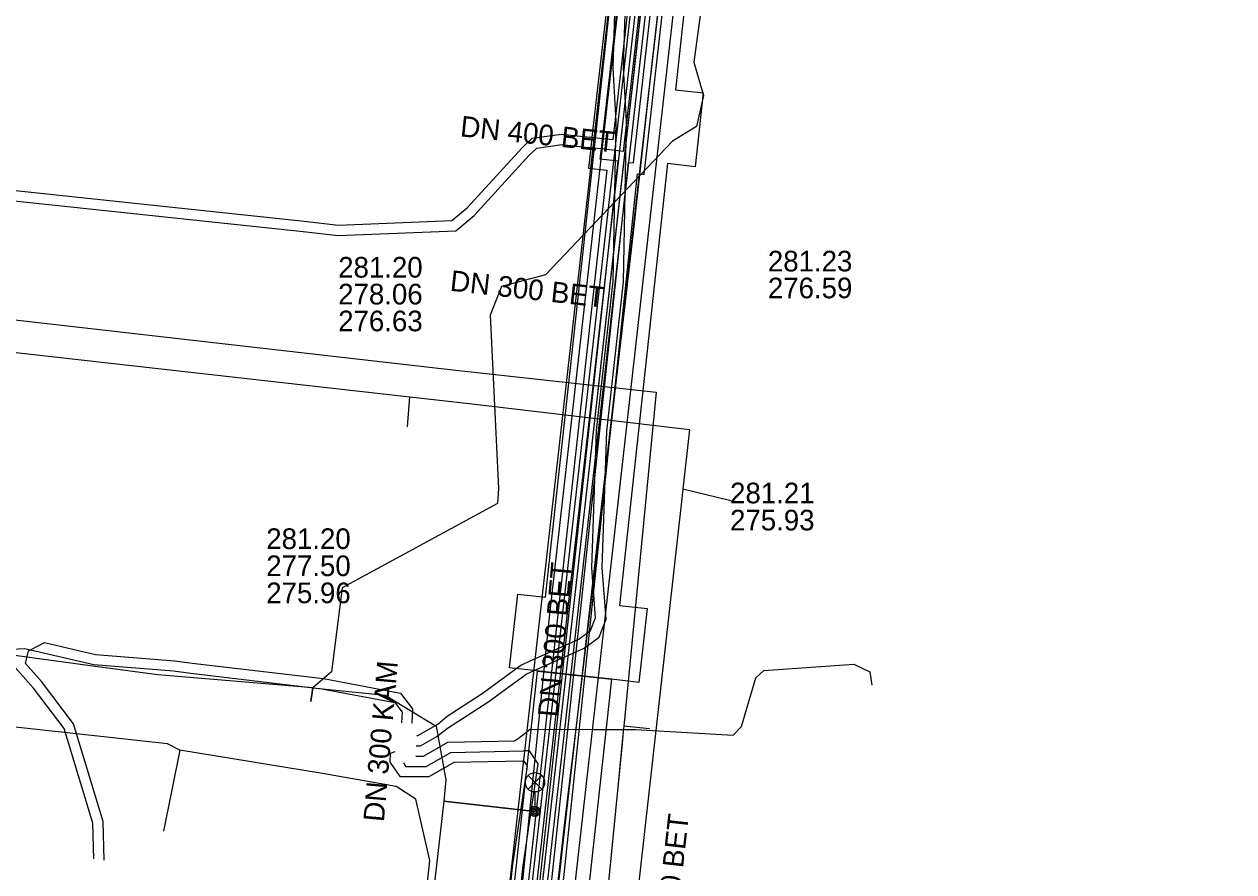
# Model space of a CAD drawing. Extents: x -595540 to -593988, y -1160850 to -1159202.
# Drawn here: x -594128.31 to -594081.46, y -1160371.96 to -1160339.11 of the extents above; entities that cross this region are included whole.
import ezdxf

# ---------------------------------------------------------------- set-up
doc = ezdxf.new("R2010")
doc.units = 0
for name, color, linetype in [('BVK-DESTOVA_popisy', 7, 'Continuous'), ('BVK-DESTOVA_trasa sítě', 7, 'Continuous'), ('BVK-KANALIZACE_ vyřazená trasa sítě', 7, 'Continuous'), ('BVK-SPLASKOVA_popisy', 7, 'Continuous'), ('BVK-SPLASKOVA_trasa sítě', 7, 'Continuous'), ('BVK-VODOVOD_trasa sítě', 7, 'Continuous'), ('BVK-VODOVOD_trasa zrušené sítě', 7, 'Continuous'), ('CETIN_kabel podzemní', 7, 'Continuous'), ('DESTOVA_trasa neprovozované sítě', 7, 'Continuous'), ('DSP-NN-TEPLARNY_kabel', 7, 'Continuous'), ('EON-NN_kabel', 7, 'Continuous'), ('EON-VN_kabel', 7, 'Continuous'), ('SPLASKOVA_neprovozovaná  trasa sítě', 7, 'Continuous'), ('TEPLARNY-ELEKTRO_kabel', 7, 'Continuous'), ('TEPLARNY-HORKOVODY_trasa sítě', 7, 'Continuous'), ('TEPLARNY-HORKOVODY_trasa sítě obvodem', 7, 'Continuous'), ('TSB_kabel VO', 7, 'Continuous'), ('TSB_kolektor', 7, 'Continuous'), ('TSB_lampy VO', 7, 'Continuous')]:
    doc.layers.add(name, color=color, linetype=linetype)

msp = doc.modelspace()

# ---------------------------------------------------------------- linework, layer by layer
at = {"layer": 'BVK-DESTOVA_popisy'}
for p, q in [((-594100.971, -1160357.808), (-594100.971, -1160357.808)), ((-594118.938, -1160360.103), (-594118.938, -1160360.103))]:
    msp.add_line(p, q, dxfattribs=at)
at = {"layer": 'BVK-DESTOVA_trasa sítě'}
msp.add_line((-594111.075, -1160353.812), (-594102.539, -1160354.822), dxfattribs=at)
for points in [[(-594159.261, -1160348.383), (-594113.381, -1160353.552), (-594111.075, -1160353.812)], [(-594102.539, -1160354.822), (-594102.799, -1160357.137), (-594102.811, -1160357.247), (-594102.852, -1160357.611), (-594105.877, -1160384.565), (-594105.882, -1160384.615), (-594105.901, -1160384.78), (-594106.212, -1160387.553)]]:
    msp.add_lwpolyline(points, dxfattribs=at)
at = {"layer": 'BVK-KANALIZACE_ vyřazená trasa sítě'}
msp.add_lwpolyline([(-594105.111, -1160366.52), (-594105.157, -1160366.996), (-594105.336, -1160368.828)], dxfattribs=at)
at = {"layer": 'BVK-SPLASKOVA_popisy'}
for p, q in [((-594116.151, -1160348.135), (-594116.151, -1160348.135)), ((-594099.507, -1160347.896), (-594099.507, -1160347.896))]:
    msp.add_line(p, q, dxfattribs=at)
at = {"layer": 'BVK-SPLASKOVA_trasa sítě'}
for p, q in [((-594159.664, -1160347.043), (-594111.588, -1160352.525)), ((-594111.588, -1160352.525), (-594103.829, -1160353.38)), ((-594105.11, -1160366.52), (-594105.33, -1160368.81)), ((-594105.33, -1160368.81), (-594107.088, -1160386.792))]:
    msp.add_line(p, q, dxfattribs=at)
msp.add_lwpolyline([(-594103.829, -1160353.38), (-594105.09, -1160366.319), (-594105.11, -1160366.52)], dxfattribs=at)
at = {"layer": 'BVK-VODOVOD_trasa sítě'}
msp.add_lwpolyline([(-594103.42, -1160335.63), (-594104.1, -1160341.57), (-594104.76, -1160347.52), (-594105.45, -1160353.45), (-594106.12, -1160359.4), (-594106.82, -1160365.34), (-594107.38, -1160370.05), (-594107.74, -1160373.14), (-594107.936, -1160374.896), (-594107.96, -1160375.11), (-594108.36, -1160378.71), (-594108.45, -1160379.55), (-594109.1, -1160385.5), (-594109.66, -1160390.25), (-594109.85, -1160391.65), (-594110.51, -1160397.57), (-594111.2, -1160403.53), (-594111.87, -1160409.48)], dxfattribs=at)
at = {"layer": 'BVK-VODOVOD_trasa zrušené sítě'}
msp.add_lwpolyline([(-594115.62, -1160443.55), (-594109.61, -1160390.38), (-594108.22, -1160378.32), (-594107.91, -1160375.21), (-594107.884, -1160374.982), (-594107.47, -1160371.19), (-594099.17, -1160298.41), (-594097.23, -1160281.2), (-594094.37, -1160256.41), (-594088.99, -1160208), (-594087.61, -1160195.33), (-594087.25, -1160191.91), (-594085.5, -1160175.7), (-594082.16, -1160145.34)], dxfattribs=at)
at = {"layer": 'CETIN_kabel podzemní'}
for points in [[(-594107.97, -1160362.1), (-594096.35, -1160259)], [(-594109.14, -1160373.71), (-594107.97, -1160362.1)], [(-594122.28, -1160367.25), (-594122.76, -1160367), (-594126.06, -1160366.64), (-594143.72, -1160364.72)], [(-594122.28, -1160367.25), (-594122.92, -1160370.39)], [(-594116.76, -1160368.15), (-594122.28, -1160367.25)], [(-594112.78, -1160373.21), (-594112.6, -1160371.52), (-594113.15, -1160369.15), (-594113.9, -1160368.66), (-594116.76, -1160368.15)]]:
    msp.add_lwpolyline(points, dxfattribs=at)
at = {"layer": 'DESTOVA_trasa neprovozované sítě'}
for p, q in [((-594113.467, -1160354.716), (-594113.381, -1160353.552)), ((-594100.569, -1160357.672), (-594102.799, -1160357.137))]:
    msp.add_line(p, q, dxfattribs=at)
at = {"layer": 'DSP-NN-TEPLARNY_kabel'}
for points in [[(-594121.143, -1160464.161), (-594118.761, -1160464.427), (-594112.865, -1160411.563), (-594119.56, -1160410.802), (-594119.143, -1160407.127), (-594112.454, -1160407.887), (-594102.843, -1160322.736), (-594109.531, -1160321.976), (-594109.114, -1160318.301), (-594102.425, -1160319.061), (-594092.133, -1160228.53), (-594097.433, -1160227.929), (-594097.016, -1160224.253), (-594091.712, -1160224.855), (-594085.261, -1160166.749), (-594090.048, -1160166.163), (-594089.626, -1160162.68), (-594084.872, -1160163.243), (-594081.459, -1160132.499), (-594087.185, -1160131.862)], [(-594087.208, -1160132.061), (-594081.68, -1160132.675), (-594085.05, -1160163.028), (-594089.778, -1160162.457), (-594090.247, -1160166.304), (-594085.499, -1160166.867), (-594091.888, -1160224.634), (-594097.192, -1160224.032), (-594097.654, -1160228.105), (-594092.355, -1160228.706), (-594102.601, -1160318.839), (-594109.29, -1160318.079), (-594109.753, -1160322.152), (-594103.064, -1160322.912), (-594112.631, -1160407.665), (-594119.319, -1160406.905), (-594119.782, -1160410.978), (-594113.086, -1160411.739), (-594118.938, -1160464.206), (-594121.121, -1160463.962)], [(-594121.187, -1160464.559), (-594118.408, -1160464.869), (-594112.423, -1160411.211), (-594119.118, -1160410.45), (-594118.791, -1160407.569), (-594112.102, -1160408.329), (-594102.401, -1160322.384), (-594109.089, -1160321.624), (-594108.762, -1160318.743), (-594102.073, -1160319.503), (-594091.691, -1160228.178)], [(-594091.912, -1160228.354), (-594102.249, -1160319.282), (-594108.938, -1160318.522), (-594109.31, -1160321.8), (-594102.622, -1160322.56), (-594112.278, -1160408.108), (-594118.967, -1160407.348), (-594119.339, -1160410.626), (-594112.644, -1160411.387), (-594118.584, -1160464.648), (-594121.165, -1160464.36)]]:
    msp.add_lwpolyline(points, dxfattribs=at)
at = {"layer": 'EON-NN_kabel'}
for points in [[(-594108.673, -1160364.211), (-594106.628, -1160363.298), (-594106.048, -1160362.869), (-594105.776, -1160362.176), (-594105.923, -1160360.172), (-594105.745, -1160354.883), (-594105.1, -1160349.1), (-594104.988, -1160342.873), (-594105.096, -1160340.811), (-594104.979, -1160336.992), (-594104.048, -1160328.941), (-594103.595, -1160322.344), (-594101.313, -1160302.646), (-594100.901, -1160299.038), (-594100.59, -1160296.264), (-594099.191, -1160286.42), (-594097.862, -1160277.187), (-594097.196, -1160272.532), (-594096.092, -1160261.644), (-594096.063, -1160259.032)], [(-594108.629, -1160363.753), (-594106.83, -1160362.95), (-594106.378, -1160362.615), (-594106.182, -1160362.114), (-594106.323, -1160360.18), (-594106.145, -1160354.855), (-594105.5, -1160349.074), (-594105.388, -1160342.879), (-594105.496, -1160340.815), (-594105.379, -1160336.962), (-594104.446, -1160328.905), (-594103.993, -1160322.308), (-594101.711, -1160302.6), (-594101.299, -1160298.994), (-594100.986, -1160296.214), (-594099.587, -1160286.364), (-594098.258, -1160277.131), (-594097.594, -1160272.484), (-594096.492, -1160261.622), (-594096.463, -1160259.002)], [(-594125.615, -1160371.46), (-594125.654, -1160370.08), (-594126.76, -1160366.414), (-594127.95, -1160364.84), (-594129.282, -1160363.365), (-594129.633, -1160362.976), (-594142.758, -1160361.658), (-594147.517, -1160361.001), (-594148.582, -1160360.935), (-594149.021, -1160361.134), (-594149.297, -1160361.259), (-594161.032, -1160360.02), (-594163.191, -1160359.836), (-594166.507, -1160359.503), (-594169.409, -1160359.559), (-594171.822, -1160358.98), (-594172.101, -1160359.186), (-594171.501, -1160359.671), (-594171.153, -1160359.817), (-594170.269, -1160360.173)], [(-594146.844, -1160369.09), (-594146.739, -1160367.645), (-594148.433, -1160363.471), (-594148.601, -1160361.383), (-594148.509, -1160361.34), (-594147.557, -1160361.399), (-594142.806, -1160362.056), (-594129.579, -1160363.383), (-594129.282, -1160363.365), (-594128.296, -1160363.306), (-594128.071, -1160363.359), (-594125.619, -1160363.934), (-594122.525, -1160364.178), (-594121.858, -1160364.267), (-594116.781, -1160364.873), (-594113.956, -1160365.403), (-594113.673, -1160365.771), (-594113.694, -1160366.183)], [(-594125.214, -1160371.505), (-594125.256, -1160370.016), (-594126.398, -1160366.23), (-594127.642, -1160364.584), (-594128.265, -1160363.894), (-594128.151, -1160363.401), (-594128.071, -1160363.359), (-594127.529, -1160363.075), (-594125.557, -1160363.538), (-594122.483, -1160363.78), (-594121.808, -1160363.871), (-594116.721, -1160364.477), (-594113.732, -1160365.039), (-594113.267, -1160365.645), (-594113.295, -1160366.203)], [(-594113.146, -1160367.482), (-594112.852, -1160367.482), (-594111.899, -1160366.935), (-594109.316, -1160366.882), (-594109.131, -1160366.755), (-594108.718, -1160366.432), (-594106.247, -1160366.443), (-594104.638, -1160366.45), (-594100.848, -1160366.67), (-594100.533, -1160366.334), (-594099.969, -1160364.449), (-594099.668, -1160364.156), (-594096.182, -1160363.917), (-594095.56, -1160364.209), (-594095.484, -1160364.728)], [(-594113.107, -1160366.682), (-594113.066, -1160366.682), (-594112.292, -1160366.238), (-594111.935, -1160365.932), (-594110.576, -1160365.056), (-594109.074, -1160363.952), (-594108.629, -1160363.753)], [(-594113.127, -1160367.082), (-594112.96, -1160367.082), (-594112.336, -1160366.724), (-594111.916, -1160366.395), (-594110.35, -1160365.386), (-594108.872, -1160364.3), (-594108.673, -1160364.211)], [(-594109.013, -1160367.675), (-594111.678, -1160367.731), (-594112.64, -1160368.282), (-594113.741, -1160368.282), (-594113.774, -1160368.232), (-594113.981, -1160367.928), (-594114.135, -1160367.71), (-594114.122, -1160367.359), (-594113.938, -1160367.299)], [(-594113.626, -1160367.739), (-594113.529, -1160367.883), (-594112.747, -1160367.883), (-594111.789, -1160367.334), (-594108.974, -1160367.276)], [(-594112.353, -1160399.392), (-594111.655, -1160398.981), (-594108.998, -1160371.811), (-594108.405, -1160367.773), (-594108.737, -1160367.27), (-594108.973, -1160367.275)], [(-594112.299, -1160398.895), (-594112.032, -1160398.74), (-594109.396, -1160371.763), (-594108.823, -1160367.865), (-594108.949, -1160367.674), (-594109.012, -1160367.676)]]:
    msp.add_lwpolyline(points, dxfattribs=at)
at = {"layer": 'EON-VN_kabel'}
for points in [[(-594095.349, -1160247.589), (-594106.321, -1160343.506), (-594106.366, -1160343.901), (-594106.457, -1160344.697), (-594105.747, -1160344.778), (-594123.196, -1160503.1)], [(-594122.533, -1160503.17), (-594105.303, -1160344.425), (-594106.002, -1160344.346), (-594105.957, -1160343.948), (-594105.911, -1160343.552), (-594094.954, -1160247.658)], [(-594113.71, -1160443.5), (-594114.867, -1160443.379), (-594104.555, -1160344.913), (-594104.302, -1160344.942), (-594093.355, -1160247.757)], [(-594094.151, -1160247.679), (-594105.114, -1160344.044), (-594105.957, -1160343.948), (-594106.366, -1160343.901), (-594106.45, -1160343.892)], [(-594094.572, -1160247.833), (-594105.51, -1160343.598), (-594105.911, -1160343.552), (-594106.321, -1160343.506), (-594106.405, -1160343.496)], [(-594113.738, -1160443.898), (-594115.506, -1160443.713), (-594104.906, -1160344.47), (-594104.71, -1160344.493), (-594093.783, -1160247.981)], [(-594175.53, -1160340.821), (-594160.129, -1160342.463), (-594154.844, -1160343.027), (-594152.581, -1160343.268), (-594137.445, -1160344.911), (-594132.229, -1160345.477), (-594130.17, -1160345.805), (-594117.513, -1160347.15), (-594116.156, -1160347.3), (-594111.599, -1160347.118), (-594110.879, -1160346.528), (-594108.757, -1160344.196), (-594108.451, -1160343.916), (-594107.489, -1160343.778), (-594106.45, -1160343.892)], [(-594154.105, -1160342.703), (-594152.539, -1160342.87), (-594137.401, -1160344.513), (-594132.175, -1160345.081), (-594130.118, -1160345.409), (-594117.469, -1160346.752), (-594116.142, -1160346.9), (-594111.749, -1160346.724), (-594111.155, -1160346.238), (-594109.041, -1160343.914), (-594108.631, -1160343.538), (-594107.505, -1160343.376), (-594106.405, -1160343.496)]]:
    msp.add_lwpolyline(points, dxfattribs=at)
at = {"layer": 'SPLASKOVA_neprovozovaná  trasa sítě'}
msp.add_line((-594104.096, -1160366.416), (-594105.09, -1160366.319), dxfattribs=at)
at = {"layer": 'TEPLARNY-ELEKTRO_kabel'}
for points in [[(-594121.143, -1160464.161), (-594118.761, -1160464.427), (-594112.865, -1160411.563), (-594119.56, -1160410.802), (-594119.143, -1160407.127), (-594112.454, -1160407.887), (-594102.843, -1160322.736), (-594109.531, -1160321.976), (-594109.114, -1160318.301), (-594102.425, -1160319.061), (-594092.133, -1160228.53), (-594097.433, -1160227.929), (-594097.016, -1160224.253), (-594091.712, -1160224.855), (-594085.261, -1160166.749), (-594090.048, -1160166.163), (-594089.626, -1160162.68), (-594084.872, -1160163.243), (-594081.459, -1160132.499), (-594087.185, -1160131.862)], [(-594087.208, -1160132.061), (-594081.68, -1160132.675), (-594085.05, -1160163.028), (-594089.778, -1160162.457), (-594090.247, -1160166.304), (-594085.499, -1160166.867), (-594091.888, -1160224.634), (-594097.192, -1160224.032), (-594097.654, -1160228.105), (-594092.355, -1160228.706), (-594102.601, -1160318.839), (-594109.29, -1160318.079), (-594109.753, -1160322.152), (-594103.064, -1160322.912), (-594112.631, -1160407.665), (-594119.319, -1160406.905), (-594119.782, -1160410.978), (-594113.086, -1160411.739), (-594118.938, -1160464.206), (-594121.121, -1160463.962)], [(-594121.187, -1160464.559), (-594118.408, -1160464.869), (-594112.423, -1160411.211), (-594119.118, -1160410.45), (-594118.791, -1160407.569), (-594112.102, -1160408.329), (-594102.401, -1160322.384), (-594109.089, -1160321.624), (-594108.762, -1160318.743), (-594102.073, -1160319.503), (-594091.691, -1160228.178)], [(-594091.912, -1160228.354), (-594102.249, -1160319.282), (-594108.938, -1160318.522), (-594109.31, -1160321.8), (-594102.622, -1160322.56), (-594112.278, -1160408.108), (-594118.967, -1160407.348), (-594119.339, -1160410.626), (-594112.644, -1160411.387), (-594118.584, -1160464.648), (-594121.165, -1160464.36)]]:
    msp.add_lwpolyline(points, dxfattribs=at)
at = {"layer": 'TEPLARNY-HORKOVODY_trasa sítě'}
msp.add_line((-594102.622, -1160322.56), (-594112.278, -1160408.108), dxfattribs=at)
at = {"layer": 'TEPLARNY-HORKOVODY_trasa sítě obvodem'}
for p, q in [((-594101.24, -1160321.459), (-594111.172, -1160409.492)), ((-594104.004, -1160323.661), (-594113.38, -1160406.725))]:
    msp.add_line(p, q, dxfattribs=at)
at = {"layer": 'TSB_kabel VO'}
for points in [[(-594101.42, -1160334.227), (-594102.253, -1160334.79), (-594101.746, -1160335.916), (-594102.381, -1160340.584), (-594102.001, -1160341.882), (-594102.267, -1160343.08), (-594103.2, -1160343.65), (-594108.121, -1160348.83), (-594109.822, -1160349.277), (-594110.264, -1160350.386), (-594109.941, -1160357.104), (-594109.984, -1160357.694), (-594116.001, -1160360.959), (-594116.408, -1160364.208), (-594117.136, -1160364.834), (-594117.211, -1160365.36)], [(-594117.211, -1160365.36), (-594117.136, -1160364.834), (-594123.132, -1160364.332), (-594125.563, -1160364), (-594129.154, -1160363.519), (-594144.456, -1160362.069), (-594146.988, -1160361.632), (-594147.592, -1160361.623), (-594166.432, -1160359.813), (-594169.331, -1160359.432), (-594172.186, -1160359.14), (-594188.071, -1160357.059), (-594188.104, -1160356.661), (-594190.231, -1160356.457), (-594190.615, -1160356.908), (-594193.706, -1160356.908), (-594209.067, -1160355.224), (-594214.068, -1160354.634), (-594215.727, -1160354.856)], [(-594117.211, -1160365.36), (-594117.136, -1160364.834), (-594114.326, -1160365.121), (-594112.35, -1160366.32), (-594111.978, -1160368.395), (-594112.062, -1160369.224), (-594108.53, -1160369.619), (-594112.062, -1160369.224), (-594114.09, -1160386.91), (-594114.45, -1160390.79), (-594114.77, -1160394.63), (-594111.53, -1160394.74), (-594111.91, -1160402.54), (-594111.68, -1160402.83), (-594113.1, -1160412.85), (-594114.12, -1160420.09), (-594114.16, -1160420.38), (-594113.59, -1160421.74), (-594114.3, -1160422.73), (-594116.44, -1160439.53), (-594115.77, -1160439.63)]]:
    msp.add_lwpolyline(points, dxfattribs=at)
at = {"layer": 'TSB_kolektor'}
msp.add_lwpolyline([(-594098.434, -1160298.871), (-594103.086, -1160341.656), (-594102.008, -1160341.776), (-594102.328, -1160344.638), (-594103.397, -1160344.519), (-594105.258, -1160361.638), (-594104.18, -1160361.758), (-594104.501, -1160364.62), (-594105.569, -1160364.501), (-594109.51, -1160364.063), (-594109.189, -1160361.201), (-594108.12, -1160361.32), (-594104.536, -1160328.353)], dxfattribs=at)
msp.add_lwpolyline([(-594111.579, -1160392.923), (-594109.86, -1160377.305), (-594111.532, -1160377.119), (-594111.213, -1160374.257), (-594109.547, -1160374.443), (-594108.432, -1160364.183), (-594105.569, -1160364.501), (-594106.685, -1160374.761), (-594105.607, -1160374.881), (-594105.927, -1160377.743), (-594106.998, -1160377.624), (-594108.717, -1160393.24)], close=True, dxfattribs=at)
at = {"layer": 'TSB_lampy VO'}
for p, q in [((-594108.795, -1160368.759), (-594108.265, -1160368.229)), ((-594108.795, -1160368.229), (-594108.265, -1160368.759)), ((-594108.795, -1160368.759), (-594108.265, -1160368.229)), ((-594108.795, -1160368.229), (-594108.265, -1160368.759)), ((-594108.53, -1160368.869), (-594108.53, -1160369.619)), ((-594108.53, -1160368.869), (-594108.53, -1160369.619))]:
    msp.add_line(p, q, dxfattribs=at)
for centre, radius in [((-594108.53, -1160368.494), 0.375), ((-594108.53, -1160368.494), 0.375), ((-594108.53, -1160369.619), 0.2), ((-594108.53, -1160369.619), 0.2), ((-594108.53, -1160369.619), 0.145), ((-594108.53, -1160369.619), 0.145), ((-594108.53, -1160369.619), 0.0876), ((-594108.53, -1160369.619), 0.0876)]:
    msp.add_circle(centre, radius, dxfattribs=at)

# ---------------------------------------------------------------- texts
at = {"layer": 'BVK-DESTOVA_popisy'}
for s, rotation, p in [('DN 400 BET', 354, (-594111.45, -1160343.458)), ('DN 500 BET', 83.5945, (-594103.233, -1160375.736))]:
    msp.add_text(s, height=0.8, rotation=rotation, dxfattribs=at).set_placement(p)
for s, p in [('281.21', (-594100.971, -1160357.683)), ('275.93', (-594100.971, -1160358.733)), ('281.20', (-594118.938, -1160359.453)), ('277.50', (-594118.938, -1160360.503)), ('275.96', (-594118.938, -1160361.553))]:
    msp.add_text(s, height=0.8, dxfattribs=at).set_placement(p)
at = {"layer": 'BVK-SPLASKOVA_popisy'}
for s, p in [('281.20', (-594116.151, -1160348.935)), ('281.23', (-594099.507, -1160348.696)), ('278.06', (-594116.151, -1160349.975)), ('276.59', (-594099.507, -1160349.736)), ('276.63', (-594116.151, -1160351.015))]:
    msp.add_text(s, height=0.8, dxfattribs=at).set_placement(p)
for s, rotation, p in [('DN 300 BET', 353.6868, (-594111.844, -1160349.442)), ('DN 300 BET', 85, (-594107.622, -1160365.988)), ('DN 300 KAM', 85, (-594114.382, -1160370.047))]:
    msp.add_text(s, height=0.8, rotation=rotation, dxfattribs=at).set_placement(p)

doc.saveas('drawing.dxf')
